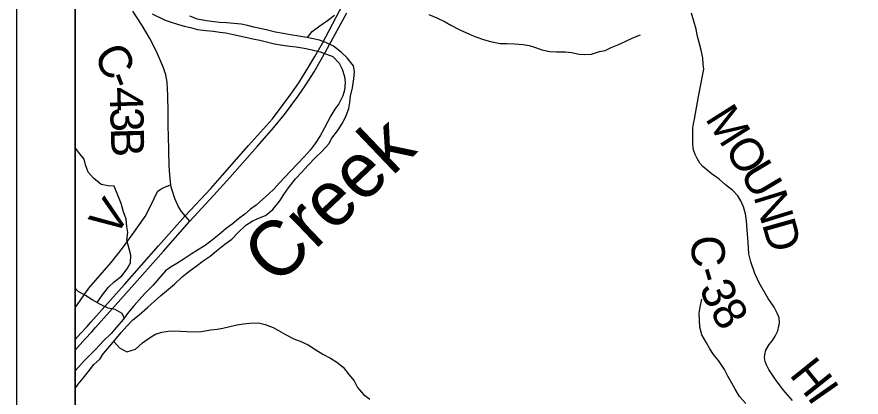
# Model space of a CAD drawing. Extents: x -13.7 to 34, y 0 to 32.3.
# Drawn here: x 23.417 to 24.865, y 17.233 to 17.887 of the extents above; entities that cross this region are included whole.
import ezdxf

# ---------------------------------------------------------------- set-up
doc = ezdxf.new("R2010")
doc.units = 0
for name, color, linetype in [('GM_X_Corporation', 7, 'Continuous'), ('GM_X_County_Road', 7, 'Continuous'), ('GM_X_County_Road_Text', 7, 'Continuous'), ('GM_X_Major_River', 7, 'Continuous'), ('GM_X_Major_River_Text', 7, 'Continuous'), ('GM_X_Minor_River', 7, 'Continuous'), ('GM_X_State_Route', 7, 'Continuous'), ('GM_X_Township_Road', 7, 'Continuous'), ('GM_X_Township_Road_Text', 7, 'Continuous'), ('SH_Data', 7, 'Continuous')]:
    doc.layers.add(name, color=color, linetype=linetype)

msp = doc.modelspace()

# ---------------------------------------------------------------- linework, layer by layer
at = {"layer": 'GM_X_Corporation'}
for points in [[(26.0026, 20.9), (23.5167, 20.9), (23.5167, 14.1)], [(26.0026, 20.9), (23.5167, 20.9), (23.5167, 15.1495)]]:
    msp.add_lwpolyline(points, dxfattribs=at)
at = {"layer": 'GM_X_County_Road'}
for points in [[(23.6765, 17.6976), (23.6764, 17.7067), (23.6764, 17.7233), (23.6756, 17.7512), (23.6743, 17.7743), (23.672, 17.7871), (23.6685, 17.7991), (23.6564, 17.8272), (23.645, 17.8492), (23.6315, 17.8718), (23.6157, 17.8963)], [(24.7475, 17.2273), (24.7319, 17.2457), (24.7185, 17.2637), (24.7072, 17.2808), (24.7029, 17.2886), (24.7009, 17.2942), (24.6999, 17.3011), (24.7, 17.3061), (24.702, 17.3138), (24.7078, 17.3238), (24.7132, 17.3307), (24.7177, 17.338), (24.7228, 17.3472), (24.7244, 17.3549), (24.7252, 17.361), (24.7249, 17.3694), (24.7215, 17.3774), (24.7162, 17.3877), (24.7058, 17.4028), (24.6904, 17.4295), (24.6831, 17.4454), (24.6765, 17.4657), (24.673, 17.4792), (24.6715, 17.4989), (24.6701, 17.5204), (24.6686, 17.5363), (24.6668, 17.5483), (24.6636, 17.5602), (24.6592, 17.5707), (24.6538, 17.579), (24.6456, 17.5884), (24.6326, 17.5979), (24.6218, 17.6078), (24.6079, 17.6176), (24.5939, 17.6295), (24.5889, 17.6351), (24.584, 17.643), (24.5806, 17.65), (24.578, 17.658), (24.5765, 17.6664), (24.5767, 17.674), (24.5765, 17.6818), (24.5767, 17.6876), (24.5768, 17.696), (24.5777, 17.7025), (24.5796, 17.7106), (24.5864, 17.7496), (24.5953, 17.7969), (24.5947, 17.805), (24.5936, 17.8161), (24.5908, 17.8291), (24.5878, 17.8424), (24.5849, 17.8529), (24.5823, 17.8652), (24.5742, 17.8927)], [(23.7137, 17.5356), (23.7055, 17.5446), (23.699, 17.5519), (23.6937, 17.5611), (23.6877, 17.5744), (23.6827, 17.5905), (23.6814, 17.5946), (23.6806, 17.5982), (23.6791, 17.6148), (23.6779, 17.6311), (23.6766, 17.6825), (23.6765, 17.6976)]]:
    msp.add_lwpolyline(points, dxfattribs=at)
at = {"layer": 'GM_X_Major_River'}
for points in [[(23.6406, 17.3873), (23.652, 17.3975), (23.663, 17.407), (23.6767, 17.4188), (23.6873, 17.4275), (23.7002, 17.44), (23.712, 17.4491), (23.7245, 17.4582), (23.7363, 17.4673), (23.7481, 17.4753), (23.7591, 17.4843), (23.7736, 17.4961), (23.7853, 17.5044), (23.7956, 17.5154), (23.8097, 17.5287), (23.8207, 17.5355), (23.8302, 17.5401), (23.8431, 17.545), (23.856, 17.5556), (23.8678, 17.5704), (23.8747, 17.5814), (23.883, 17.5928), (23.8948, 17.608), (23.9051, 17.6193), (23.9165, 17.6319), (23.929, 17.6448), (23.94, 17.6554), (23.9518, 17.6683), (23.9572, 17.6781), (23.967, 17.6907), (23.9754, 17.7039), (23.9815, 17.7168), (23.9864, 17.7293), (23.988, 17.7392), (23.9891, 17.7502), (23.9926, 17.7643), (23.9952, 17.7798), (23.996, 17.7927), (23.9945, 17.8026), (23.9835, 17.8159), (23.9729, 17.8261), (23.96, 17.8364), (23.9471, 17.8425), (23.9361, 17.8463), (23.9254, 17.8489), (23.914, 17.8512), (23.9004, 17.8535), (23.8863, 17.8558), (23.8734, 17.8577), (23.8605, 17.8604), (23.8468, 17.8634), (23.8339, 17.8665), (23.8233, 17.8688), (23.8123, 17.8718), (23.8013, 17.8737), (23.7891, 17.8752), (23.7766, 17.8764), (23.7648, 17.8771), (23.7553, 17.8779), (23.7421, 17.8798), (23.7269, 17.8825), (23.7132, 17.8878)], [(23.649, 17.8917), (23.6711, 17.8806), (23.6817, 17.8772), (23.6923, 17.8742), (23.7037, 17.8707), (23.7147, 17.8681), (23.7265, 17.8647), (23.7409, 17.8631), (23.7538, 17.862), (23.7648, 17.8604), (23.7755, 17.8589), (23.7857, 17.857), (23.7986, 17.854), (23.8119, 17.8513), (23.8214, 17.849), (23.8335, 17.8464), (23.8453, 17.8437), (23.8586, 17.8403), (23.8688, 17.8384), (23.8848, 17.8364), (23.8958, 17.8349), (23.9095, 17.833), (23.9235, 17.8296), (23.9372, 17.8262), (23.9482, 17.8227), (23.9588, 17.8182), (23.9698, 17.8068), (23.9751, 17.7965), (23.9789, 17.784), (23.98, 17.7738), (23.9789, 17.7605), (23.9758, 17.751), (23.969, 17.7373), (23.9625, 17.7278), (23.9557, 17.7165), (23.9504, 17.7066), (23.9446, 17.696), (23.937, 17.6819), (23.9283, 17.669), (23.9199, 17.6577), (23.9097, 17.6459), (23.899, 17.6345), (23.8865, 17.6216), (23.8675, 17.6012), (23.858, 17.5913), (23.8485, 17.5818), (23.839, 17.5735), (23.8272, 17.5632), (23.8177, 17.556), (23.8078, 17.5473), (23.7972, 17.5394), (23.7861, 17.5306), (23.7759, 17.5227), (23.7637, 17.5128), (23.7523, 17.5037)], [(23.7523, 17.5037), (23.7398, 17.4935), (23.7265, 17.4855), (23.7158, 17.4787), (23.7018, 17.4696), (23.6911, 17.4628), (23.6816, 17.4571), (23.6718, 17.4499), (23.66, 17.437), (23.6497, 17.4252), (23.636, 17.4112), (23.6265, 17.4006), (23.6178, 17.3907), (23.6083, 17.3793), (23.5988, 17.3664), (23.5881, 17.3539), (23.5782, 17.3425), (23.5653, 17.3297), (23.5516, 17.3152), (23.5417, 17.305), (23.5322, 17.2955), (23.5224, 17.2849), (23.5167, 17.2781)], [(23.5167, 17.2481), (23.522, 17.2553), (23.5303, 17.2655), (23.541, 17.2796), (23.5489, 17.2891), (23.5592, 17.2985), (23.5653, 17.308), (23.5759, 17.3205), (23.5957, 17.3441), (23.6056, 17.355), (23.6159, 17.3657), (23.6265, 17.3748), (23.6406, 17.3873)]]:
    msp.add_lwpolyline(points, dxfattribs=at)
at = {"layer": 'GM_X_Minor_River'}
for points in [[(23.9152, 17.851), (23.9234, 17.8615), (23.9363, 17.871), (23.9495, 17.8805), (23.962, 17.8896)], [(24.1237, 17.8906), (24.1374, 17.8849), (24.1514, 17.8777), (24.1613, 17.8721), (24.1779, 17.8634), (24.1923, 17.8573), (24.2026, 17.8528), (24.2189, 17.8471), (24.2295, 17.8441), (24.2462, 17.8407), (24.2568, 17.8407), (24.2704, 17.8404), (24.2856, 17.8392), (24.2958, 17.8374), (24.3064, 17.8336), (24.3174, 17.8298), (24.3314, 17.8268), (24.3428, 17.8264), (24.3583, 17.8264), (24.3685, 17.8253), (24.3818, 17.8227), (24.3916, 17.8216), (24.4026, 17.8223), (24.4163, 17.8269), (24.4261, 17.8288), (24.4363, 17.8338), (24.4481, 17.8383), (24.4606, 17.844), (24.4738, 17.8505), (24.4871, 17.8558)], [(23.5543, 17.3957), (23.5637, 17.409), (23.5739, 17.4223), (23.5838, 17.4314), (23.5966, 17.4416), (23.6057, 17.4534), (23.6118, 17.464), (23.6125, 17.4773), (23.6091, 17.4879), (23.6053, 17.5031), (23.6068, 17.516), (23.6056, 17.5266), (23.6041, 17.5387), (23.5999, 17.5516), (23.5957, 17.5656), (23.59, 17.5804), (23.5836, 17.5956), (23.5733, 17.5963), (23.5612, 17.5986), (23.5483, 17.6092), (23.5392, 17.6194), (23.5343, 17.6323), (23.532, 17.6418), (23.5225, 17.6543), (23.5167, 17.6618)], [(23.6008, 17.3692), (23.5975, 17.3768), (23.5853, 17.3836), (23.5732, 17.3858), (23.5599, 17.3923), (23.5459, 17.4006), (23.5342, 17.4078), (23.5217, 17.4146), (23.5167, 17.4206)], [(24.6678, 17.2224), (24.6568, 17.2345), (24.6492, 17.247), (24.6435, 17.2572), (24.637, 17.2694), (24.6313, 17.2804), (24.6207, 17.2959), (24.612, 17.3065), (24.6059, 17.3163), (24.6002, 17.3262), (24.5919, 17.3402), (24.5888, 17.3531), (24.5873, 17.3774), (24.5895, 17.388), (24.5922, 17.4017)], [(23.5828, 17.3287), (23.593, 17.318), (23.6055, 17.3112), (23.6203, 17.3158), (23.632, 17.3264), (23.6445, 17.3351), (23.6543, 17.3416), (23.6657, 17.3446), (23.6801, 17.3473), (23.6975, 17.3466), (23.7085, 17.3458), (23.7206, 17.3451), (23.7335, 17.3462), (23.749, 17.3485), (23.7604, 17.3501), (23.7702, 17.3516), (23.782, 17.3547), (23.7948, 17.3573), (23.8055, 17.3592), (23.8161, 17.3604), (23.8312, 17.3608), (23.8426, 17.3578), (23.8562, 17.3529), (23.8657, 17.3476), (23.8774, 17.3408), (23.8918, 17.3336), (23.9028, 17.3294), (23.9165, 17.323), (23.9298, 17.3147), (23.9419, 17.3071), (23.9548, 17.3003), (23.9658, 17.2931), (23.9768, 17.2848), (23.9866, 17.2719), (23.9953, 17.2613), (24.0014, 17.2495), (24.0117, 17.2378), (24.0223, 17.2295)]]:
    msp.add_lwpolyline(points, dxfattribs=at)
at = {"layer": 'GM_X_State_Route'}
for points in [[(23.5167, 17.332), (23.5259, 17.3424), (23.5373, 17.3546), (23.5434, 17.3618), (23.6011, 17.4267), (23.6599, 17.493), (23.7054, 17.5444), (23.7055, 17.5446), (23.7493, 17.5919), (23.7697, 17.6148), (23.8144, 17.6653), (23.8551, 17.7112), (23.8736, 17.7357), (23.887, 17.7535), (23.9005, 17.7732), (23.9159, 17.7982), (23.9281, 17.8183), (23.9411, 17.8413), (23.9763, 17.9076)], [(23.5167, 17.3138), (23.534, 17.3334), (23.5454, 17.3456), (23.5516, 17.3528), (23.6092, 17.4177), (23.6681, 17.484), (23.7137, 17.5356), (23.7549, 17.5803), (23.7823, 17.6108), (23.8298, 17.6646), (23.8573, 17.6957), (23.876, 17.7187), (23.899, 17.7496), (23.9127, 17.7698), (23.9267, 17.7923), (23.9463, 17.8264), (23.9828, 17.8937)]]:
    msp.add_lwpolyline(points, dxfattribs=at)
at = {"layer": 'GM_X_Township_Road'}
for points in [[(23.6524, 17.5746), (23.6559, 17.5818), (23.6586, 17.5872), (23.6642, 17.5912), (23.6729, 17.5953), (23.6806, 17.5982)], [(23.5167, 17.3866), (23.54, 17.4201), (23.5786, 17.4643), (23.5978, 17.4893), (23.6146, 17.5119), (23.637, 17.5436), (23.6498, 17.5692), (23.6524, 17.5746)]]:
    msp.add_lwpolyline(points, dxfattribs=at)
at = {"layer": 'SH_Data'}
for points in [[(23.4167, 21), (30.4167, 21), (30.4167, 14), (23.4167, 14)], [(23.5167, 20.9), (30.3167, 20.9), (30.3167, 14.1), (23.5167, 14.1)]]:
    msp.add_lwpolyline(points, close=True, dxfattribs=at)

# ---------------------------------------------------------------- texts
at = {"layer": 'GM_X_County_Road_Text'}
for s, rotation, p in [('C', 297.9214, (23.547, 17.8218)), ('-', 291.6507, (23.5681, 17.7821)), ('4', 271.8426, (23.5757, 17.7654)), ('M', 302.3022, (24.5967, 17.7118)), ('3', 271.4886, (23.5768, 17.7306)), ('B', 271.4521, (23.5777, 17.6956)), ('O', 302.2977, (24.6296, 17.6597)), ('U', 300.9207, (24.6561, 17.6177)), ('N', 287.2184, (24.6804, 17.5781)), ('D', 285.7983, (24.6951, 17.5307)), ('C', 274.5792, (24.5725, 17.5088)), ('-', 286.505, (24.5786, 17.4496)), ('3', 292.1929, (24.5872, 17.4214)), ('8', 301.2445, (24.6049, 17.3803)), ('H', 308.7281, (24.741, 17.2714)), ('I', 305.0195, (24.7717, 17.2332))]:
    msp.add_text(s, height=0.0568, rotation=rotation, dxfattribs=at).set_placement(p)
at = {"layer": 'GM_X_Major_River_Text'}
msp.add_text('Creek', height=0.0947, rotation=43.6532, dxfattribs=at).set_placement((23.8616, 17.4221))
at = {"layer": 'GM_X_Township_Road_Text'}
msp.add_text('V', height=0.0568, rotation=54.7313, dxfattribs=at).set_placement((23.5839, 17.5061))

doc.saveas('drawing.dxf')
